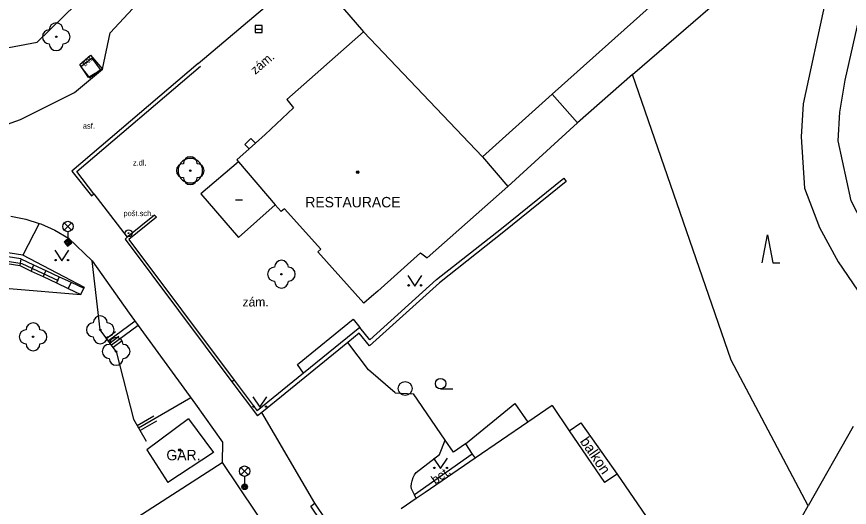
# Model space of a CAD drawing. Extents: x -598233 to -596890, y -1157848 to -1156431.
# Drawn here: x -597463.2 to -597403.3, y -1157315.5 to -1157280.2 of the extents above; entities that cross this region are included whole.
import ezdxf

# ---------------------------------------------------------------- set-up
doc = ezdxf.new("R2010")
doc.units = 0
for name, color, linetype in [('Level 10', 7, 'Continuous'), ('Level 11', 7, 'Continuous'), ('Level 14', 7, 'Continuous'), ('Level 15', 7, 'Continuous'), ('Level 22', 7, 'Continuous'), ('Level 23', 7, 'Continuous'), ('Level 24', 7, 'Continuous'), ('Level 25', 7, 'Continuous'), ('Level 26', 7, 'Continuous'), ('Level 27', 7, 'Continuous'), ('Level 33', 7, 'Continuous'), ('Level 36', 7, 'Continuous'), ('Level 39', 7, 'Continuous'), ('Level 40', 7, 'Continuous'), ('Level 41', 7, 'Continuous'), ('Level 42', 7, 'Continuous'), ('Level 5', 7, 'Continuous'), ('Level 7', 7, 'Continuous'), ('Level 8', 7, 'Continuous'), ('Level 9', 7, 'Continuous')]:
    doc.layers.add(name, color=color, linetype=linetype)

msp = doc.modelspace()

# ---------------------------------------------------------------- linework, layer by layer
at = {"layer": 'Level 10'}
for points in [[(-597450.17, -1157283.58), (-597442.17, -1157276.8)], [(-597456.5, -1157281.37), (-597454.56, -1157279.3)], [(-597457.06, -1157284), (-597456.5, -1157281.37)], [(-597450.17, -1157283.58), (-597459.26, -1157291.33)], [(-597459.08, -1157285.68), (-597457.06, -1157284)], [(-597462.97, -1157287.62), (-597459.08, -1157285.68)], [(-597467.15, -1157289.1), (-597462.97, -1157287.62)], [(-597459.26, -1157291.33), (-597457.86, -1157293.09)], [(-597457.86, -1157293.09), (-597457.68, -1157292.96)], [(-597457.68, -1157292.96), (-597455.28, -1157296.08)], [(-597463.67, -1157294.57), (-597462.57, -1157294.79), (-597461.62, -1157295.08), (-597461.5, -1157295.12), (-597460.48, -1157295.58), (-597459.51, -1157296.14)], [(-597459.51, -1157296.14), (-597457.81, -1157297.77)], [(-597457.81, -1157297.77), (-597455.13, -1157301.55)], [(-597455.13, -1157301.55), (-597450.37, -1157308.08)], [(-597450.37, -1157308.08), (-597448.41, -1157310.81), (-597448.45, -1157312.27)], [(-597441.77, -1157315.21), (-597445.59, -1157308.68)]]:
    msp.add_lwpolyline(points, dxfattribs=at)
at = {"layer": 'Level 11'}
for points in [[(-597362.94, -1157237.26), (-597365.85, -1157238.21), (-597400.18, -1157297.99), (-597401.46, -1157296.78), (-597403.17, -1157293.45), (-597404.09, -1157289.14), (-597403.99, -1157287.08), (-597403.6, -1157284.79), (-597402.44, -1157279.71), (-597402.24, -1157276.6599), (-597402.55, -1157272.28), (-597403.3, -1157269.39), (-597404.38, -1157266.4699), (-597406.18, -1157263.46), (-597408.4, -1157258.85), (-597409.43, -1157256.07), (-597410.15, -1157252.9099), (-597410.58, -1157244.37)], [(-597412.92, -1157247.84), (-597412.54, -1157254.07), (-597411.95, -1157256.9), (-597409.9, -1157261.6), (-597406.23, -1157268.11), (-597405.23, -1157271.5), (-597404.84, -1157275.78), (-597405.02, -1157279.05), (-597406.61, -1157286.49), (-597406.77, -1157288.85), (-597406.52, -1157292.55), (-597405.45, -1157295.38), (-597404.11, -1157297.86), (-597402.71, -1157299.88), (-597401.12, -1157301.39), (-597399.17, -1157302.96)], [(-597418.9, -1157284.37), (-597408.95, -1157275.77), (-597407.89, -1157274.38)], [(-597458.69, -1157283.66), (-597457.93, -1157282.98)], [(-597457.93, -1157282.98), (-597457.06, -1157284)], [(-597458.9, -1157291.36), (-597450.01, -1157283.77)], [(-597458.07, -1157284.6), (-597458.69, -1157283.66)], [(-597457.06, -1157284), (-597458.07, -1157284.6)], [(-597418.9, -1157284.37), (-597422.86, -1157287.84), (-597427.87, -1157292.44)], [(-597406.25, -1157315.39), (-597411.8, -1157304.9099), (-597418.9, -1157284.37)], [(-597424.68, -1157285.8), (-597422.86, -1157287.84)], [(-597457.68, -1157292.96), (-597458.9, -1157291.36)], [(-597459.81, -1157296.4), (-597459.51, -1157296.14)], [(-597459.51, -1157296.14), (-597459.26, -1157296.47)], [(-597459.81, -1157296.4), (-597459.57, -1157296.71)], [(-597459.57, -1157296.71), (-597459.26, -1157296.47)], [(-597466.98, -1157297.5), (-597463.02, -1157298.12)], [(-597462.95, -1157297.64), (-597466.9, -1157297.01)], [(-597462.95, -1157297.64), (-597463.02, -1157298.12)], [(-597463.02, -1157298.12), (-597462.2, -1157298.51), (-597461.34, -1157298.91), (-597460.36, -1157299.37), (-597459.53, -1157299.76), (-597458.62, -1157300.19)], [(-597462.95, -1157297.64), (-597462.03, -1157298.07), (-597461.13, -1157298.48), (-597460.17, -1157298.93), (-597459.32, -1157299.32), (-597458.4, -1157299.75)], [(-597462.03, -1157298.07), (-597462.2, -1157298.51)], [(-597461.13, -1157298.48), (-597461.34, -1157298.91)], [(-597460.17, -1157298.93), (-597460.36, -1157299.37)], [(-597459.32, -1157299.32), (-597459.53, -1157299.76)], [(-597442.58, -1157305.85), (-597443.03, -1157305.24), (-597439.02, -1157301.96), (-597438.54, -1157302.56)], [(-597430.92, -1157310.94), (-597427.37, -1157308.03), (-597426.45, -1157309.38)], [(-597423.46, -1157310), (-597422.63, -1157309.43), (-597420.01, -1157313.12)], [(-597403.01, -1157309.7), (-597406.25, -1157315.39)], [(-597432.8, -1157311.71), (-597432.39, -1157310.67)], [(-597434.7, -1157313.37), (-597434.6, -1157313.16), (-597434.49, -1157312.99), (-597432.8, -1157311.71)], [(-597430.44, -1157311.67), (-597434.61, -1157314.6)], [(-597434.61, -1157314.6), (-597434.82, -1157314.17), (-597434.83, -1157314.01), (-597434.81, -1157313.78), (-597434.77, -1157313.59), (-597434.7, -1157313.37)], [(-597434.48, -1157314.88), (-597434.61, -1157314.6)], [(-597431.38, -1157330.61), (-597441.77, -1157315.21)], [(-597407.49, -1157317.56), (-597406.25, -1157315.39)]]:
    msp.add_lwpolyline(points, dxfattribs=at)
at = {"layer": 'Level 14'}
for points in [[(-597461.76, -1157282.04), (-597458.97, -1157279.34)], [(-597467.26, -1157283.09), (-597461.76, -1157282.04)], [(-597457.22, -1157302.74), (-597457.81, -1157297.77)], [(-597463.79, -1157299.76), (-597458.62, -1157300.19)], [(-597456.08, -1157304.29), (-597457.22, -1157302.74)], [(-597456.08, -1157304.29), (-597454.83, -1157309.17)], [(-597454.83, -1157309.17), (-597453.92, -1157310.74)]]:
    msp.add_lwpolyline(points, dxfattribs=at)
at = {"layer": 'Level 15'}
for points in [[(-597454.72, -1157302.11), (-597456.64, -1157303.52)], [(-597456.12, -1157302.89), (-597456.76, -1157303.36)], [(-597454.49, -1157302.43), (-597456.41, -1157303.85)], [(-597455.89, -1157303.22), (-597456.52, -1157303.69)], [(-597455.65, -1157303.54), (-597456.29, -1157304.01)], [(-597450.69, -1157307.64), (-597454.46, -1157309.82)], [(-597453.37, -1157308.96), (-597454.56, -1157309.64)], [(-597453.17, -1157309.3), (-597454.35, -1157309.99)]]:
    msp.add_lwpolyline(points, dxfattribs=at)
at = {"layer": 'Level 22'}
for centre in [(-597460.39, -1157281.66), (-597450.74, -1157291.29), (-597444.18, -1157298.74), (-597457.22, -1157302.74), (-597462.06, -1157303.24), (-597456.08, -1157304.29)]:
    msp.add_circle(centre, 0.05, dxfattribs=at)
for centre, start, end in [((-597460.39, -1157281.16), 0, 180), ((-597460.89, -1157281.66), 90, 270), ((-597459.89, -1157281.66), 270, 90), ((-597460.39, -1157282.16), 180, 0), ((-597450.74, -1157290.79), 0, 180), ((-597451.24, -1157291.29), 90, 270), ((-597450.24, -1157291.29), 270, 90), ((-597450.74, -1157291.79), 180, 0), ((-597444.18, -1157298.24), 0, 180), ((-597444.68, -1157298.74), 90, 270), ((-597443.68, -1157298.74), 270, 90), ((-597444.18, -1157299.24), 180, 0), ((-597457.22, -1157302.24), 0, 180), ((-597462.06, -1157302.74), 0, 180), ((-597457.72, -1157302.74), 90, 270), ((-597456.72, -1157302.74), 270, 90), ((-597462.56, -1157303.24), 90, 270), ((-597461.56, -1157303.24), 270, 90), ((-597457.22, -1157303.24), 180, 0), ((-597456.08, -1157303.79), 0, 180), ((-597462.06, -1157303.74), 180, 0), ((-597456.58, -1157304.29), 90, 270), ((-597455.58, -1157304.29), 270, 90), ((-597456.08, -1157304.79), 180, 0)]:
    msp.add_arc(centre, 0.5, start, end, dxfattribs=at)
at = {"layer": 'Level 23'}
msp.add_lwpolyline([(-597461.62, -1157295.08), (-597462.79, -1157297.38)], dxfattribs=at)
at = {"layer": 'Level 24'}
for points in [[(-597446.37, -1157288.98), (-597446.82, -1157289.4)], [(-597446.37, -1157288.98), (-597446.05, -1157289.32)], [(-597446.82, -1157289.4), (-597446.51, -1157289.73)]]:
    msp.add_lwpolyline(points, dxfattribs=at)
at = {"layer": 'Level 25'}
for radius in [0.25, 0.0303]:
    msp.add_circle((-597455.18, -1157295.79), radius, dxfattribs=at)
at = {"layer": 'Level 26'}
msp.add_lwpolyline([(-597458.0044, -1157284.6108), (-597457.2092, -1157284.0044), (-597457.8156, -1157283.2092), (-597458.6108, -1157283.8156)], close=True, dxfattribs=at)
at = {"layer": 'Level 27'}
msp.add_line((-597446.06, -1157281.11), (-597445.56, -1157281.11), dxfattribs=at)
msp.add_lwpolyline([(-597446.06, -1157281.36), (-597445.56, -1157281.36), (-597445.56, -1157280.86), (-597446.06, -1157280.86)], close=True, dxfattribs=at)
msp.add_circle((-597435.27, -1157306.96), 0.5, dxfattribs=at)
at = {"layer": 'Level 33'}
for p, q in [((-597459.815, -1157295.57), (-597459.285, -1157295.04)), ((-597459.815, -1157295.04), (-597459.285, -1157295.57)), ((-597459.55, -1157295.68), (-597459.55, -1157296.43)), ((-597447.095, -1157313.17), (-597446.565, -1157312.64)), ((-597447.095, -1157312.64), (-597446.565, -1157313.17)), ((-597446.83, -1157313.28), (-597446.83, -1157314.03))]:
    msp.add_line(p, q, dxfattribs=at)
for centre, radius in [((-597459.55, -1157295.305), 0.375), ((-597459.55, -1157296.43), 0.2), ((-597459.55, -1157296.43), 0.1445), ((-597459.55, -1157296.43), 0.0876), ((-597446.83, -1157312.905), 0.375), ((-597446.83, -1157314.03), 0.2), ((-597446.83, -1157314.03), 0.1445), ((-597446.83, -1157314.03), 0.0876)]:
    msp.add_circle(centre, radius, dxfattribs=at)
at = {"layer": 'Level 36'}
msp.add_line((-597432.72, -1157306.985), (-597431.845, -1157306.985), dxfattribs=at)
for points in [[(-597409.559, -1157297.918), (-597409.184, -1157295.918), (-597408.809, -1157297.918), (-597408.309, -1157297.918)], [(-597460.49, -1157297.02), (-597459.99, -1157297.77), (-597459.49, -1157297.02)], [(-597435.07, -1157298.84), (-597434.57, -1157299.59), (-597434.07, -1157298.84)], [(-597446.23, -1157307.56), (-597445.73, -1157308.31), (-597445.23, -1157307.56)], [(-597433.22, -1157311.97), (-597432.72, -1157312.72), (-597432.22, -1157311.97)]]:
    msp.add_lwpolyline(points, dxfattribs=at)
for centre, radius in [((-597460.4402, -1157297.7198), 0.05), ((-597459.5408, -1157297.7198), 0.05), ((-597435.0202, -1157299.5398), 0.05), ((-597434.1208, -1157299.5398), 0.05), ((-597432.7201, -1157306.6099), 0.375), ((-597446.1802, -1157308.2598), 0.05), ((-597445.2808, -1157308.2598), 0.05), ((-597433.1702, -1157312.6698), 0.05), ((-597432.2708, -1157312.6698), 0.05)]:
    msp.add_circle(centre, radius, dxfattribs=at)
at = {"layer": 'Level 39'}
msp.add_line((-597447.49, -1157293.39), (-597446.99, -1157293.39), dxfattribs=at)
for centre, radius in [((-597438.69, -1157291.4), 0.09), ((-597438.69, -1157291.4), 0.0398), ((-597451.5, -1157311.38), 0.09), ((-597451.5, -1157311.38), 0.0398)]:
    msp.add_circle(centre, radius, dxfattribs=at)
at = {"layer": 'Level 5'}
for points in [[(-597410.26, -1157272.9), (-597424.68, -1157285.8)], [(-597440.24, -1157279.03), (-597438.28, -1157281.31)], [(-597438.28, -1157281.31), (-597443.79, -1157286.17)], [(-597438.28, -1157281.31), (-597429.7, -1157290.3)], [(-597443.79, -1157286.17), (-597443.32, -1157286.76)], [(-597424.68, -1157285.8), (-597429.7, -1157290.3)], [(-597443.32, -1157286.76), (-597445.35, -1157288.69)], [(-597445.35, -1157288.69), (-597446.05, -1157289.32), (-597446.51, -1157289.73), (-597447.39, -1157290.52)], [(-597429.7, -1157290.3), (-597427.87, -1157292.44)], [(-597447.28, -1157290.65), (-597449.97, -1157292.95)], [(-597447.39, -1157290.52), (-597447.28, -1157290.65), (-597444.62, -1157293.75), (-597444.19, -1157294.23)], [(-597427.87, -1157292.44), (-597433.69, -1157297.55)], [(-597449.97, -1157292.95), (-597447.28, -1157296.09)], [(-597444.62, -1157293.75), (-597447.28, -1157296.09)], [(-597443.9699, -1157294.03), (-597444.19, -1157294.23)], [(-597443.9699, -1157294.03), (-597441.34, -1157296.94)], [(-597441.34, -1157296.94), (-597441.56, -1157297.14)], [(-597441.56, -1157297.14), (-597438.24, -1157300.83)], [(-597434.16, -1157297.21), (-597437.25, -1157299.95), (-597437.69, -1157300.35), (-597438.24, -1157300.83)], [(-597434.16, -1157297.21), (-597433.69, -1157297.55)], [(-597424.7, -1157308.19), (-597426.45, -1157309.38)], [(-597424.7, -1157308.19), (-597423.46, -1157310)], [(-597450.87, -1157309.13), (-597453.88, -1157311.38)], [(-597450.87, -1157309.13), (-597449.06, -1157311.55)], [(-597426.45, -1157309.38), (-597430.24, -1157311.98), (-597433.82, -1157314.43)], [(-597423.46, -1157310), (-597420.9099, -1157313.7199)], [(-597453.88, -1157311.38), (-597452.35, -1157313.71)], [(-597449.06, -1157311.55), (-597452.35, -1157313.71)], [(-597420.01, -1157313.12), (-597420.9099, -1157313.7199)], [(-597420.01, -1157313.12), (-597417.6599, -1157316.54)], [(-597433.82, -1157314.43), (-597434.48, -1157314.88), (-597435.57, -1157315.62)]]:
    msp.add_lwpolyline(points, dxfattribs=at)
at = {"layer": 'Level 7'}
for points in [[(-597449.8559, -1157291.2912), (-597449.8693, -1157291.138), (-597449.9091, -1157290.9894), (-597449.9741, -1157290.8499), (-597450.0624, -1157290.7239), (-597450.1712, -1157290.6152), (-597450.2972, -1157290.5269), (-597450.4366, -1157290.4619), (-597450.5852, -1157290.4221), (-597450.7384, -1157290.4087), (-597450.8917, -1157290.4221), (-597451.0403, -1157290.4619), (-597451.1797, -1157290.5269), (-597451.3057, -1157290.6152), (-597451.4145, -1157290.724), (-597451.5027, -1157290.85), (-597451.5677, -1157290.9894), (-597451.6075, -1157291.138), (-597451.6209, -1157291.2912), (-597451.6075, -1157291.4445), (-597451.5677, -1157291.5931), (-597451.5027, -1157291.7325), (-597451.4144, -1157291.8585), (-597451.3057, -1157291.9673), (-597451.1797, -1157292.0555), (-597451.0402, -1157292.1205), (-597450.8916, -1157292.1603), (-597450.7384, -1157292.1737), (-597450.5852, -1157292.1603), (-597450.4366, -1157292.1205), (-597450.2971, -1157292.0555), (-597450.1711, -1157291.9672), (-597450.0624, -1157291.8585), (-597449.9741, -1157291.7325), (-597449.9091, -1157291.593), (-597449.8693, -1157291.4444), (-597449.8559, -1157291.2912)], [(-597428.34, -1157295.45), (-597423.86, -1157291.83)], [(-597423.86, -1157291.83), (-597423.68, -1157292.06), (-597428.17, -1157295.69)], [(-597462.79, -1157297.38), (-597488.51, -1157293.31)], [(-597453.31, -1157294.48), (-597455.28, -1157296.08), (-597455.44, -1157296.21)], [(-597453.31, -1157294.48), (-597453.18, -1157294.64)], [(-597453.18, -1157294.64), (-597455.16, -1157296.24)], [(-597433.01, -1157299.13), (-597428.34, -1157295.45)], [(-597428.17, -1157295.69), (-597432.81, -1157299.35)], [(-597455.44, -1157296.21), (-597447.74, -1157306.48), (-597445.9, -1157308.93)], [(-597455.16, -1157296.24), (-597447.58, -1157306.36), (-597445.93, -1157308.57)], [(-597458.35, -1157299.69), (-597462.79, -1157297.38)], [(-597432.81, -1157299.35), (-597437.84, -1157303.88)], [(-597433.01, -1157299.13), (-597437.81, -1157303.45)], [(-597458.62, -1157300.19), (-597458.4, -1157299.75)], [(-597458.4, -1157299.75), (-597458.35, -1157299.69)], [(-597438.54, -1157302.56), (-597442.58, -1157305.85), (-597445.93, -1157308.57)], [(-597437.81, -1157303.45), (-597438.54, -1157302.56)], [(-597438.58, -1157302.98), (-597439.39, -1157303.64), (-597445.59, -1157308.68), (-597445.9, -1157308.93)], [(-597437.84, -1157303.88), (-597438.58, -1157302.98)], [(-597435.98, -1157307.28), (-597437.91, -1157305.62), (-597439.39, -1157303.64)], [(-597447.58, -1157306.36), (-597447.74, -1157306.48)], [(-597430.92, -1157310.94), (-597431.8, -1157311.53), (-597432.39, -1157310.67), (-597434.68, -1157307.34)], [(-597455.25, -1157316.66), (-597448.45, -1157312.27)], [(-597448.45, -1157312.27), (-597436.26, -1157330.44)], [(-597431.7199, -1157330.73), (-597442.07, -1157315.42), (-597441.77, -1157315.21)]]:
    msp.add_lwpolyline(points, dxfattribs=at)
at = {"layer": 'Level 8'}
for points in [[(-597435.98, -1157307.28), (-597434.68, -1157307.34)], [(-597430.92, -1157310.94), (-597430.44, -1157311.67), (-597430.24, -1157311.98)]]:
    msp.add_lwpolyline(points, dxfattribs=at)
at = {"layer": 'Level 9'}
for points in [[(-597476.94, -1157295.69), (-597462.87, -1157297.96)], [(-597462.87, -1157297.96), (-597460.25, -1157299.2)]]:
    msp.add_lwpolyline(points, dxfattribs=at)

# ---------------------------------------------------------------- texts
at = {"layer": 'Level 40'}
for s, height, rotation, p in [('bet.', 0.4, 42, (-597458.32, -1157283.82)), ('zám.', 0.65, 40.346647, (-597446.06, -1157284.41)), ('bet.', 0.65, 35.036194, (-597433.11, -1157313.88))]:
    msp.add_text(s, height=height, rotation=rotation, dxfattribs=at).set_placement(p)
for s, height, p in [('asf.', 0.4, (-597458.47, -1157288.27)), ('z.dl.', 0.4, (-597454.87, -1157290.92)), ('zám.', 0.65, (-597446.98, -1157301.06))]:
    msp.add_text(s, height=height, dxfattribs=at).set_placement(p)
at = {"layer": 'Level 41'}
for s, p in [('RESTAURACE', (-597442.46, -1157293.93)), ('GAR.', (-597452.46, -1157312.12))]:
    msp.add_text(s, height=0.75, dxfattribs=at).set_placement(p)
at = {"layer": 'Level 42'}
msp.add_text('pošt.sch.', height=0.4, dxfattribs=at).set_placement((-597455.55, -1157294.56))
msp.add_text('balkon', height=0.75, rotation=304.359992, dxfattribs=at).set_placement((-597422.72, -1157310.76))

doc.saveas('drawing.dxf')
